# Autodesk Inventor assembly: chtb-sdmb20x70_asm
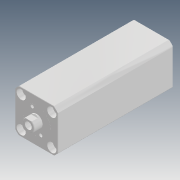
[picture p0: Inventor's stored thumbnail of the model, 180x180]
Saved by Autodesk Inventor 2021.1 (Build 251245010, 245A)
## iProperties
Company: Microsoft
Created: 2018-05
Part Number: chtb-sdmb20x70_asm
Description: STEP AP214
Document SubType Name: Assembly
Designer: user
Title: chtb-sdmb20x70_asm.STEP
Author: Windows
Revision Number: ÈÎºÎ
Sending System: SolidWorks 2015
Preprocessor: SwSTEP 2.0
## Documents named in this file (4)
- D:\Vault_2016\Projekty\Clamptek\Hydraulic\CHTB\CHTB-20\Inventor\CHTB-SDMB20x70\chtb-sdmb20x70_asm.iam
- D:\Vault_2016\Projekty\Clamptek\Hydraulic\CHTB\CHTB-20\Inventor\CHTB-SDMB20x70\CHTB-SDMB20X70NBT.ipt
- D:\Vault_2016\Projekty\Clamptek\Hydraulic\CHTB\CHTB-20\Inventor\CHTB-SDMB20x70\CHTB-SDMB20X70NHSG.ipt
- D:\Vault_2016\Projekty\Clamptek\Hydraulic\CHTB\CHTB-20\Inventor\CHTB-SDMB20x70\QG_3.ipt
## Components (3 placed, 3 different names)
1. CHTB-SDMB20X70NBT_1
2. CHTB-SDMB20X70NHSG_2
3. QG_3_3
